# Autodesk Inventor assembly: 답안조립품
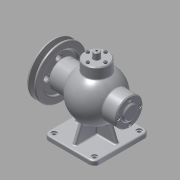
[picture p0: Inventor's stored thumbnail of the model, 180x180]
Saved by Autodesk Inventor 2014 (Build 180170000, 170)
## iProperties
Created: 2015-10
Part Number: 답안조립품
Document SubType Name: Assembly
Designer: youjin05
Author: youjin05
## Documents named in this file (19)
- D:\451010V1012\답안조립품.iam
- C:\Users\youjin05\Desktop\451010V1012\본체.ipt
- C:\Users\youjin05\Desktop\451010V1012\뒤커버.ipt
- C:\Users\youjin05\Desktop\451010V1012\앞커버.ipt
- C:\Users\youjin05\Desktop\451010V1012\상부커버.ipt
- C:\Users\youjin05\Desktop\451010V1012\베어링- 6202.ipt
- KS B 2023 - 6202 - 15 x 35 x 11 - 7.8.ipt
- C:\Users\youjin05\Desktop\451010V1012\오일실 15 30 7.ipt
- C:\Users\youjin05\Desktop\451010V1012\멈춤링- 15 x 1.ipt
- C:\Users\youjin05\Desktop\451010V1012\멈춤링- 35x1.6.ipt
- KS B 1336 - 35x1.6.ipt
- C:\Users\youjin05\Desktop\451010V1012\부시.ipt
- C:\Users\youjin05\Desktop\451010V1012\편심축.ipt
- C:\Users\youjin05\Desktop\451010V1012\슬라이드.ipt
- C:\Users\youjin05\Desktop\451010V1012\볼트 M4 x 16.ipt
- C:\Users\youjin05\Desktop\451010V1012\볼트 M 4 x 12.ipt
- C:\Users\youjin05\Desktop\451010V1012\키 4 x 4 x 12.ipt
- C:\Users\youjin05\Desktop\451010V1012\V-벨트풀리.ipt
- C:\Users\youjin05\Desktop\451010V1012\너트 M8.ipt
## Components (16 placed, 5 different names)
1. KS B 2023 - 6202 - 15 x 35 x 11 - 7.8:1 — 각도:2
2. KS B 2023 - 6202 - 15 x 35 x 11 - 7.8:2 — 각도:1
3. KS B 1336 - 35x1.6:1
4. V-벨트풀리:1
5. ISO 4762 M4 x 16:2
6. ISO 4762 M4 x 16:3
7. ISO 4762 M4 x 16:4
8. ISO 4762 M4 x 16:5
9. ISO 4762 M4 x 16:1
10. ISO 4762 M4 x 16:6
11. ISO 4762 M4 x 16:7
12. ISO 4762 M4 x 16:8
13. KS B 1021 - 에 따름 ISO 1207 - 미터 A  M 4 x 12:1
14. KS B 1021 - 에 따름 ISO 1207 - 미터 A  M 4 x 12:2
15. KS B 1021 - 에 따름 ISO 1207 - 미터 A  M 4 x 12:3
16. KS B 1021 - 에 따름 ISO 1207 - 미터 A  M 4 x 12:4
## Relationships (2: Angle 2)
- 각도:1 [Angle]: KS B 2023 - 6202 - 15 x 35 x 11 - 7.8:2
- 각도:2 [Angle]: KS B 2023 - 6202 - 15 x 35 x 11 - 7.8:1
